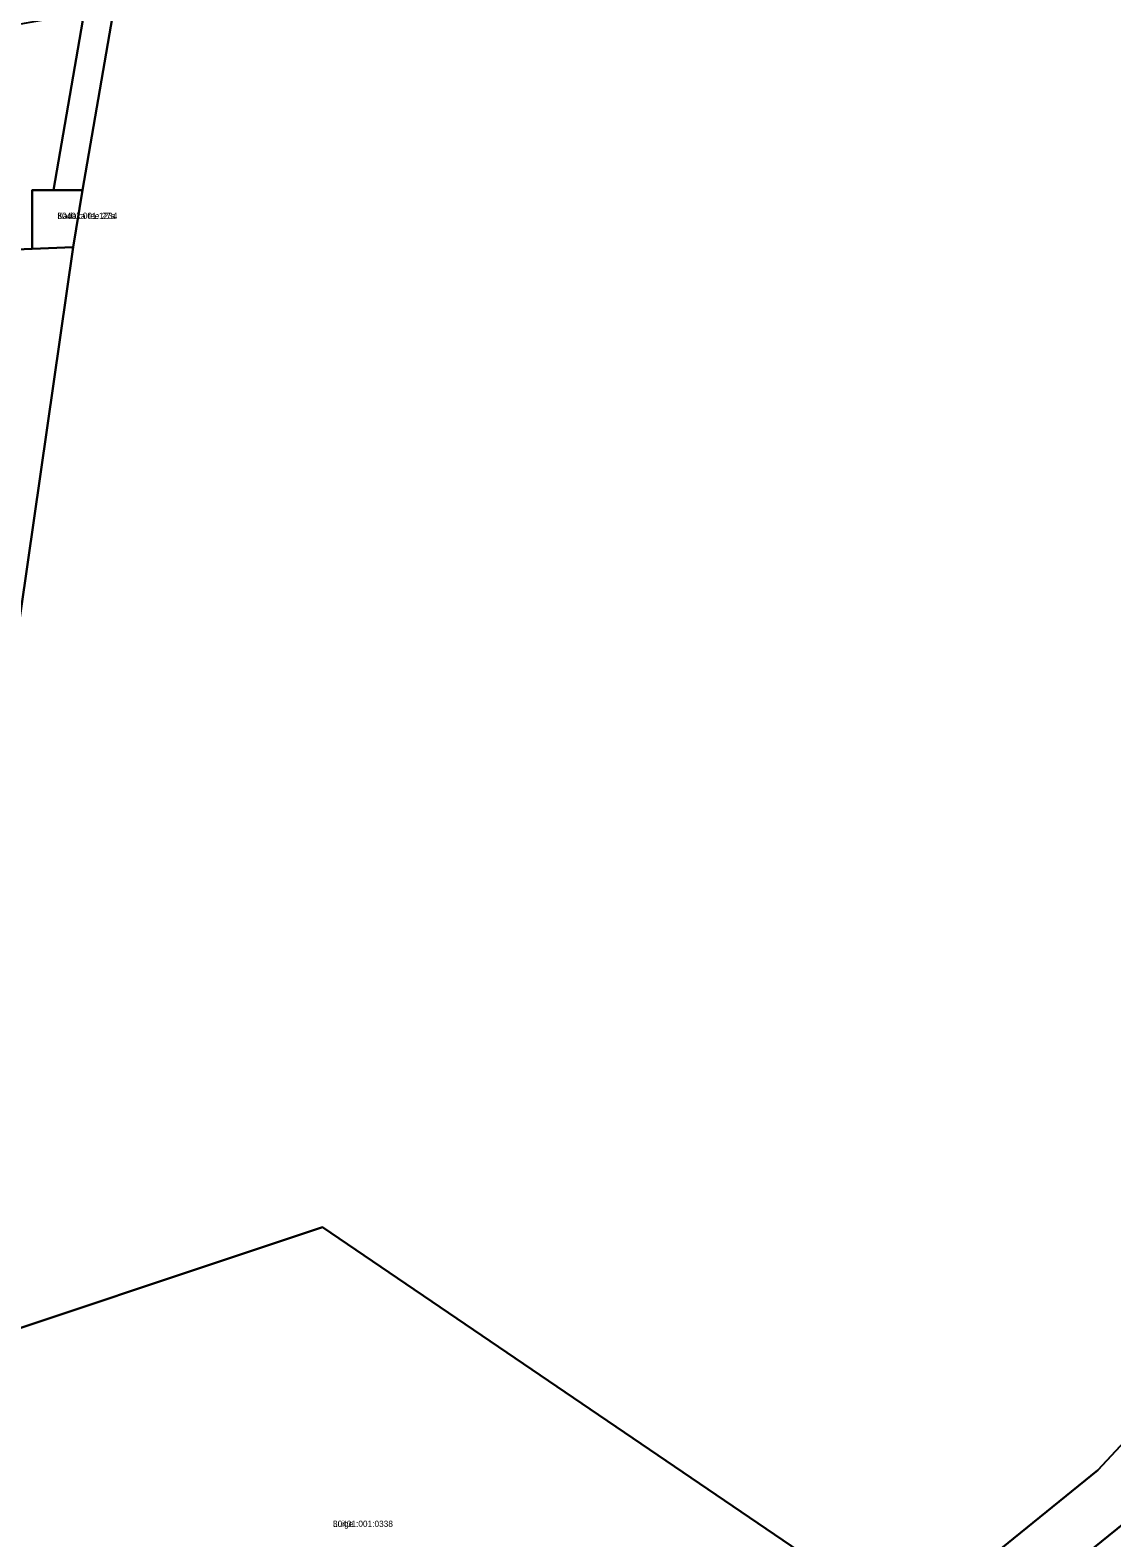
# Model space of a CAD drawing. Extents: x 542681 to 554572, y 6566489 to 6580482.
# Drawn here: x 547084.3 to 547346, y 6576513.1 to 6576877.8 of the extents above; entities that cross this region are included whole.
import ezdxf

# ---------------------------------------------------------------- set-up
doc = ezdxf.new("R2010")
doc.units = 0
for name, color, linetype in [('L_AADRESS', 7, 'Continuous'), ('PIIR', 7, 'Continuous'), ('TUNNUS', 7, 'Continuous')]:
    doc.layers.add(name, color=color, linetype=linetype)

msp = doc.modelspace()

# ---------------------------------------------------------------- linework, layer by layer
at = {"layer": 'PIIR'}
for points in [[(547012.16, 6576877.81), (547024.4, 6576877.91), (547041.73, 6576890.69), (547055.83, 6576871.88), (547062.94, 6576870.92), (547071.06, 6576875.81), (547079.8, 6576878.99), (547087.99, 6576880.38), (547097.08, 6576880.27), (547089.99, 6576839.14), (547084.8, 6576839.14), (547084.8, 6576824.93), (547012.97, 6576821.97)], [(547380.13, 6576847.05), (547380.13, 6576857.03), (547588.14, 6576880.74), (547519.16, 6576337.62), (547305.45, 6576486.01), (547317.24, 6576491.02), (547352.3, 6576519.4), (547368.79, 6576537.02), (547375.84, 6576551.75), (547379.04, 6576678.28)], [(547084.8, 6576839.14), (547089.99, 6576839.14), (547097.02, 6576839.14), (547094.71, 6576825.34), (547084.8, 6576824.93)], [(547012.97, 6576821.97), (547084.8, 6576824.93), (547094.71, 6576825.34), (547080.51, 6576726.7), (547028.83, 6576738.65), (547027.24, 6576777.51), (547014.82, 6576776.99)], [(547055.9, 6576555.22), (547155.04, 6576588.29), (547292.82, 6576494.6), (547295.63, 6576492.69), (547269.97, 6576481.74), (547238.16, 6576469.95), (547220.51, 6576468.98), (547145.42, 6576474.95), (547121.53, 6576472.37), (547094.23, 6576457.75), (547074.32, 6576443.23), (547051.96, 6576492.07)]]:
    msp.add_lwpolyline(points, close=True, dxfattribs=at)
for points in [[(547357.84, 6576545.81), (547342.59, 6576529.51), (547309.83, 6576502.97), (547292.82, 6576494.6), (547155.04, 6576588.29), (547055.9, 6576555.22), (547060.6, 6576587.66), (547065.51, 6576621.92), (547070.27, 6576655.21), (547075.25, 6576689.98), (547080.51, 6576726.7), (547094.71, 6576825.34), (547097.02, 6576839.14), (547104.27, 6576881.11)], [(547104.27, 6576881.11), (547097.02, 6576839.14), (547089.99, 6576839.14), (547097.08, 6576880.27)], [(547309.83, 6576502.97), (547342.59, 6576529.51), (547357.84, 6576545.81)], [(547352.3, 6576519.4), (547317.24, 6576491.02)]]:
    msp.add_lwpolyline(points, dxfattribs=at)

# ---------------------------------------------------------------- texts
at = {"layer": 'L_AADRESS'}
for s, p in [('Kadaka tee 27a', (547090.91, 6576832.16)), ('Luige', (547157.57, 6576515.76))]:
    msp.add_text(s, height=1.5, dxfattribs=at).set_placement(p)
at = {"layer": 'TUNNUS'}
for s, p in [('30401:001:1234', (547090.91, 6576832.16)), ('30401:001:0338', (547157.57, 6576515.76))]:
    msp.add_text(s, height=1.5, dxfattribs=at).set_placement(p)

doc.saveas('drawing.dxf')
